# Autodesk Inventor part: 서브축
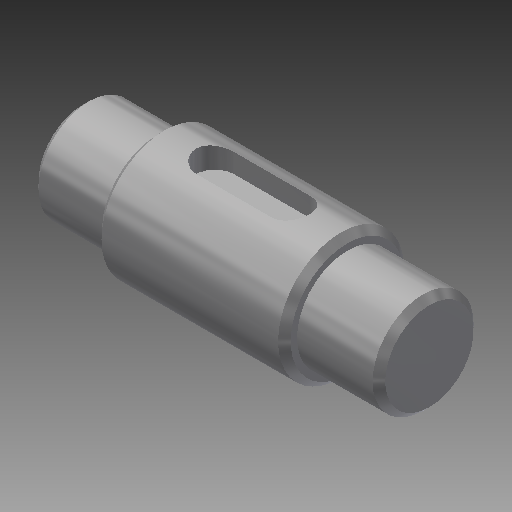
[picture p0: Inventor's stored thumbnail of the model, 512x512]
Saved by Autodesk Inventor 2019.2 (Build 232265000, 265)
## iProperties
Created: 2019-03
Part Number: 서브축
Material: 강철, 연강
Document SubType Name: Modeling
Designer: mduedu
Density: 1 g/cm^3
Appearance: 강철
Author: mduedu
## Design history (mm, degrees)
sketch "스케치1"
  geometry: L1 (0, 0)-(12, 0); L2 (12, 0)-(12, 8); L3 (12, 8)-(0, 8); L4 (0, 8)-(0, 0); L5 (12, 0)-(42, 0); L6 (42, 0)-(42, 10); L7 (42, 10)-(12, 10); L8 (12, 10)-(12, 0); L9 (42, 0)-(55, 0); L10 (55, 0)-(55, 8); L11 (55, 8)-(42, 8); L12 (42, 8)-(42, 0)
  constraints: 24 end point, 6 parallel, 3 horizontal, 3 perpendicular
  dimensions: "d0" = 16 diameter of L3 L1; "d2" = 20 diameter of L7 L5; "d3" = 16 diameter of L11 L9; "d4" = 12 distance of L2.end L3.end; "d5" = 30 distance of L6.end L7.end; "d6" = 55 distance between parallel lines of L10 L4
revolve "회전1" sketch "스케치1" stored, may be unused: angle "d7" = 90 deg
node "작업 평면1"
sketch "스케치2" dims "d10" = 18
  geometry: L1 (6, -3)-(-6, -3); L2 (-6, -3)-(-6, 3); L3 (-6, 3)-(6, 3); L4 (6, 3)-(6, -3); L5 (15, 10)-(15, -10) reference; 3 further points
  constraints: 8 end point, 2 midpoint, 2 parallel, 2 vertical alignment, 1 horizontal, 1 horizontal alignment, 1 perpendicular, 4 other
  dimensions: "d8" = 6 distance between parallel lines of L3 L1; "d11" = 6 dimension on L5
extrude "돌출1" cut sketch "스케치2" distance "d12" = 3.5; taper "d13" = 0 deg
chamfer "모따기1" distance "d14" = 1; stored, may be unused: second distance "d15" = 2, angle "d16" = 45 deg
chamfer "모따기2" distance "d17" = 1; stored, may be unused: second distance "d18" = 2, angle "d19" = 45 deg
node "솔리드1"
